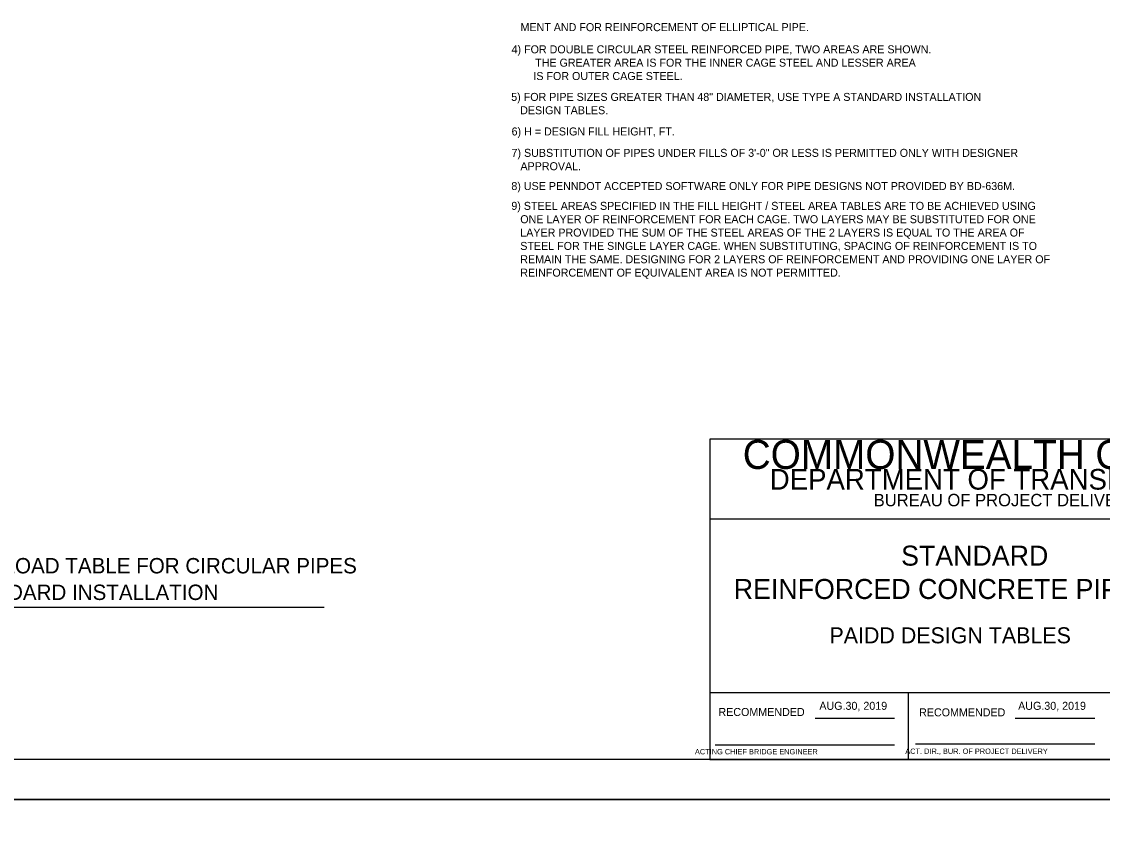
# Model space of a CAD drawing. Extents: x -22562 to -18409, y 3991 to 7171.
# Drawn here: x -20016.8 to -19611.7, y 4577.9 to 4876.9 of the extents above; entities that cross this region are included whole.
import ezdxf

# ---------------------------------------------------------------- set-up
doc = ezdxf.new("R2010")
doc.units = 0
for name, color, linetype in [('1', 7, 'Continuous'), ('2', 7, 'Continuous'), ('4', 7, 'Continuous'), ('PLT-BNDY', 7, 'Continuous')]:
    doc.layers.add(name, color=color, linetype=linetype)

msp = doc.modelspace()

# ---------------------------------------------------------------- linework, layer by layer
at = {"layer": '2'}
for p, q in [((-19558.85, 4720.37), (-19758.85, 4720.37)), ((-19758.85, 4720.37), (-19758.85, 4600.37)), ((-19558.85, 4690.37), (-19758.85, 4690.37)), ((-20075.15, 4657.41), (-19903.38, 4657.41)), ((-19558.85, 4625.37), (-19758.85, 4625.37)), ((-19684.35, 4600.37), (-19684.35, 4625.37)), ((-19719.38, 4615.87), (-19689.62, 4615.87)), ((-19644.38, 4615.87), (-19614.47, 4615.87)), ((-19756.85, 4605.87), (-19689.62, 4605.87)), ((-19681.72, 4606.24), (-19614.47, 4606.24)), ((-19558.85, 4600.37), (-20344.85, 4600.37)), ((-19758.85, 4600.37), (-19558.85, 4600.37))]:
    msp.add_line(p, q, dxfattribs=at)
at = {"layer": 'PLT-BNDY'}
for points in [[(-20384.85, 5179.37), (-19543.85, 5179.37), (-19543.85, 4585.37), (-20384.85, 4585.37)], [(-20384.85, 4585.37), (-19543.85, 4585.37), (-19543.85, 3991.37), (-20384.85, 3991.37)]]:
    msp.add_lwpolyline(points, close=True, dxfattribs=at)

# ---------------------------------------------------------------- texts
at = {"layer": '1'}
for s, height, p in [('5) FOR PIPE SIZES GREATER THAN 48" DIAMETER, USE TYPE A STANDARD INSTALLATION', 3, (-19833.26, 4847.2)), ('   DESIGN TABLES.', 3, (-19833.26, 4842.2)), ('6) H = DESIGN FILL HEIGHT, FT.                                                                                                                  ', 3, (-19833.12, 4834.25)), ('8) USE PENNDOT ACCEPTED SOFTWARE ONLY FOR PIPE DESIGNS NOT PROVIDED BY BD-636M.', 3, (-19833.21, 4813.79)), ('9) STEEL AREAS SPECIFIED IN THE FILL HEIGHT / STEEL AREA TABLES ARE TO BE ACHIEVED USING', 3, (-19833.21, 4806.36)), ('   ONE LAYER OF REINFORCEMENT FOR EACH CAGE. TWO LAYERS MAY BE SUBSTITUTED FOR ONE', 3, (-19833.21, 4801.35)), ('   LAYER PROVIDED THE SUM OF THE STEEL AREAS OF THE 2 LAYERS IS EQUAL TO THE AREA OF', 3, (-19833.21, 4796.35)), ('   STEEL FOR THE SINGLE LAYER CAGE. WHEN SUBSTITUTING, SPACING OF REINFORCEMENT IS TO', 3, (-19833.21, 4791.34)), ('   REMAIN THE SAME. DESIGNING FOR 2 LAYERS OF REINFORCEMENT AND PROVIDING ONE LAYER OF', 3, (-19833.21, 4786.34)), ('   REINFORCEMENT OF EQUIVALENT AREA IS NOT PERMITTED.', 3, (-19833.21, 4781.33)), ('DESIGN TABLES AND PROOF TEST LOAD TABLE FOR CIRCULAR PIPES', 5.7669, (-20156.81, 4670.08)), ('- TYPE B STANDARD INSTALLATION', 5.7669, (-20076.73, 4660.11))]:
    msp.add_text(s, height=height, dxfattribs=at).set_placement(p)
at = {"layer": '2'}
for s, height, p in [('COMMONWEALTH OF PENNSYLVANIA', 10.8525, (-19746.47, 4709.24)), ('DEPARTMENT OF TRANSPORTATION', 7.7332, (-19736.35, 4701.49)), ('BUREAU OF PROJECT DELIVERY', 4.6493, (-19697.39, 4695.24)), ('STANDARD', 7.5, (-19687.1, 4672.99)), ('REINFORCED CONCRETE PIPES', 7.5, (-19749.85, 4660.49)), ('PAIDD DESIGN TABLES', 6, (-19713.97, 4643.87)), ('AUG.30, 2019', 3, (-19717.76, 4618.94)), ('AUG.30, 2019', 3, (-19643.25, 4618.94)), ('       ACTING CHIEF BRIDGE ENGINEER', 2.0002, (-19769.76, 4602.24)), ('   ACT. DIR., BUR. OF PROJECT DELIVERY', 2.0002, (-19687.84, 4602.42))]:
    msp.add_text(s, height=height, dxfattribs=at).set_placement(p)
for p in [(-19755.58, 4616.62), (-19680.36, 4616.49)]:
    msp.add_text('RECOMMENDED', height=3, rotation=360, dxfattribs=at).set_placement(p)
at = {"layer": '4'}
for s, p in [('   MENT AND FOR REINFORCEMENT OF ELLIPTICAL PIPE.', (-19833.13, 4873.35)), ('4) FOR DOUBLE CIRCULAR STEEL REINFORCED PIPE, TWO AREAS ARE SHOWN.', (-19833.13, 4865.04)), ('THE GREATER AREA IS FOR THE INNER CAGE STEEL AND LESSER AREA', (-19824.28, 4860.04)), ('IS FOR OUTER CAGE STEEL.', (-19824.96, 4855.03)), ('7) SUBSTITUTION OF PIPES UNDER FILLS OF 3\'-0" OR LESS IS PERMITTED ONLY WITH DESIGNER ', (-19833.15, 4826.23)), ('   APPROVAL.                                                                                   ', (-19833.15, 4821.22))]:
    msp.add_text(s, height=3, dxfattribs=at).set_placement(p)

doc.saveas('drawing.dxf')
